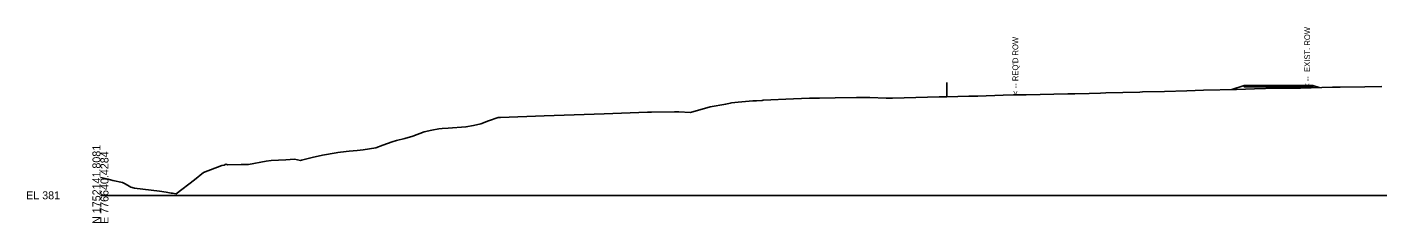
# Model space of a CAD drawing. Extents: x 776426 to 854588, y 1736205 to 1756790.
# Drawn here: x 805845.1 to 806317.6, y 1750705.1 to 1750773.7 of the extents above; entities that cross this region are included whole.
import ezdxf

# ---------------------------------------------------------------- set-up
doc = ezdxf.new("R2010")
doc.units = 0
for name, color, linetype in [('DTM CONTOURS_MAJOR_TX', 7, 'Continuous'), ('DTM_X_FLOW_ARROWS', 7, 'Continuous'), ('X_TRANS_EOP', 7, 'Continuous'), ('XS_P_DR_GRAVEL', 7, 'Continuous'), ('XS_P_GROUND', 7, 'Continuous'), ('XS_P_ROW', 7, 'Continuous'), ('XS_X_ROW', 7, 'Continuous')]:
    doc.layers.add(name, color=color, linetype=linetype)

msp = doc.modelspace()

# ---------------------------------------------------------------- linework, layer by layer
at = {"layer": 'DTM CONTOURS_MAJOR_TX'}
msp.add_line((805870.79, 1750714.76), (806370.79, 1750714.76), dxfattribs=at)
at = {"layer": 'DTM_X_FLOW_ARROWS'}
msp.add_lwpolyline([(805870.79, 1750721.04), (805873.44, 1750720.39), (805875.15, 1750719.9), (805878.5, 1750719.22), (805879.24, 1750718.86), (805880.3, 1750718.33), (805881.45, 1750717.59), (805882.66, 1750717.32), (805891.42, 1750716.22), (805893.79, 1750715.84), (805895.51, 1750715.57), (805896.02, 1750715.47), (805897.25, 1750715.34), (805903.69, 1750720.17), (805906.82, 1750722.78), (805913.26, 1750725.21), (805914.04, 1750725.34), (805914.62, 1750725.65), (805914.98, 1750725.56), (805915.32, 1750725.45), (805920, 1750725.53), (805921.68, 1750725.54), (805922.56, 1750725.56), (805928.8, 1750726.77), (805930.51, 1750726.93), (805935.66, 1750727.22), (805938.7, 1750727.38), (805940.77, 1750727), (805941.12, 1750727.03), (805944.87, 1750728.03), (805948.48, 1750728.88), (805953.21, 1750729.62), (805953.8, 1750729.75), (805954.8, 1750729.92), (805957.75, 1750730.21), (805960.59, 1750730.5), (805962.66, 1750730.72), (805967.07, 1750731.45), (805969.59, 1750732.3), (805972.87, 1750733.55), (805974.34, 1750733.91), (805977.26, 1750734.66), (805980.01, 1750735.44), (805984.05, 1750737), (805986.73, 1750737.6), (805989.12, 1750738), (805990.35, 1750738.14), (805992.4, 1750738.26), (805998.6, 1750738.73), (806001.29, 1750739.27), (806003.82, 1750739.77), (806006.56, 1750740.82), (806009.91, 1750742.04), (806010.7, 1750742.05), (806025.94, 1750742.6), (806046.96, 1750743.31), (806062.08, 1750743.83), (806063.57, 1750743.92), (806071.62, 1750743.95), (806072.72, 1750743.95), (806073.09, 1750743.95), (806077.19, 1750743.78), (806084.05, 1750745.71), (806089.47, 1750746.74), (806091.05, 1750747.02), (806091.45, 1750747.15), (806093.85, 1750747.44), (806095.08, 1750747.52), (806097.73, 1750747.74), (806098.95, 1750747.84), (806099.67, 1750747.89), (806100.24, 1750747.9), (806102.25, 1750748.01), (806102.63, 1750748.03), (806113.19, 1750748.51), (806118.75, 1750748.73), (806120.18, 1750748.83), (806122.33, 1750748.84), (806127.81, 1750748.85), (806135.18, 1750749.04), (806135.74, 1750749.05), (806139.92, 1750749.03), (806145.61, 1750748.82), (806147.84, 1750748.79), (806164.17, 1750749.24), (806164.78, 1750749.24), (806166.85, 1750749.28), (806174.5, 1750749.46), (806177.05, 1750749.52), (806177.68, 1750749.54), (806186.5, 1750749.8), (806190.12, 1750749.9), (806194.6, 1750749.99), (806209.12, 1750750.26), (806211.65, 1750750.32), (806216.6, 1750750.47), (806220.63, 1750750.58), (806222.45, 1750750.62), (806234.36, 1750750.94), (806235.25, 1750750.95), (806242.97, 1750751.15), (806250.75, 1750751.35), (806256.58, 1750751.64), (806268.12, 1750751.87), (806274.48, 1750752.03), (806282.3, 1750752.24), (806290.57, 1750752.34), (806301.77, 1750752.63), (806304.45, 1750752.68), (806313.08, 1750752.76), (806318.99, 1750752.82)], dxfattribs=at)
at = {"layer": 'X_TRANS_EOP'}
msp.add_line((806166.86, 1750754.28), (806166.86, 1750749.28), dxfattribs=at)
msp.add_line((806166.86, 1750754.28), (806166.86, 1750749.28), dxfattribs=at)
at = {"layer": 'XS_P_DR_GRAVEL'}
for points in [[(806282.79, 1750753.28), (806282.79, 1750752.78), (806270.79, 1750752.78), (806270.79, 1750753.28), (806282.79, 1750753.28)], [(806282.79, 1750753.28), (806282.79, 1750752.78), (806294.79, 1750752.78), (806294.79, 1750753.28), (806282.79, 1750753.28)]]:
    msp.add_lwpolyline(points, dxfattribs=at)
at = {"layer": 'XS_P_GROUND'}
for points in [[(806270.79, 1750753.28), (806266.49, 1750751.84)], [(806294.79, 1750753.28), (806297.09, 1750752.51)]]:
    msp.add_lwpolyline(points, dxfattribs=at)

# ---------------------------------------------------------------- texts
at = {"layer": 'DTM CONTOURS_MAJOR_TX'}
for s, p in [('N 1752141.8081', (805870.79, 1750704.76)), ('E 776640.4284', (805873.59, 1750704.76))]:
    msp.add_text(s, height=2.8, rotation=90, dxfattribs=at).set_placement(p)
msp.add_text('EL 381', height=2.8, dxfattribs=at).set_placement((805844.79, 1750713.36))
at = {"layer": 'XS_P_ROW'}
msp.add_text("< -- REQ'D ROW", height=2, rotation=90, dxfattribs=at).set_placement((806191.79, 1750749.91))
at = {"layer": 'XS_X_ROW'}
msp.add_text('< --  EXIST. ROW', height=2, rotation=90, dxfattribs=at).set_placement((806293.88, 1750752.4))

doc.saveas('drawing.dxf')
